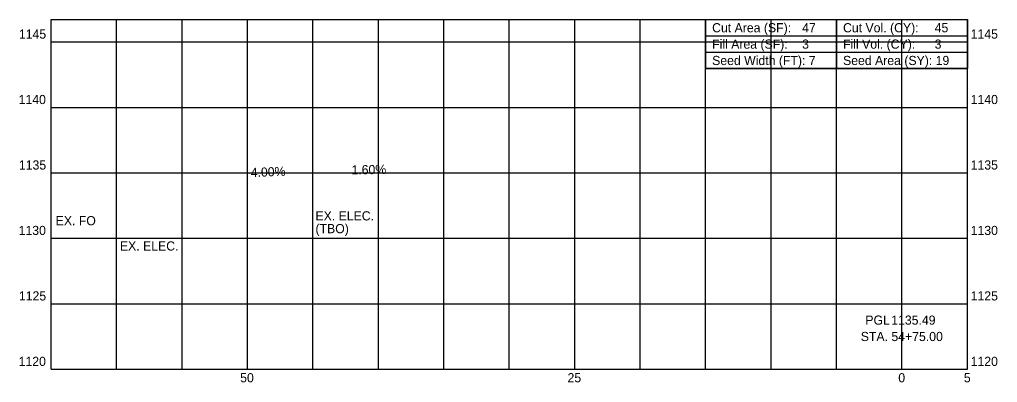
# Model space of a CAD drawing. Extents: x -67.4 to 7.3, y 1119 to 1146.7.
import ezdxf

# ---------------------------------------------------------------- set-up
doc = ezdxf.new("R2010")
doc.units = 0
for name, color, linetype in [('Default', 7, 'Continuous'), ('MD_P_Surface_Aggregate_Base', 7, 'Continuous'), ('MD_X_Concrete_Pavement', 7, 'Continuous'), ('SH_Data', 7, 'Continuous'), ('SH_Major_Grid_Line', 7, 'Continuous'), ('SH_Masking', 7, 'Continuous'), ('SH_Text', 7, 'Continuous')]:
    doc.layers.add(name, color=color, linetype=linetype)

msp = doc.modelspace()

# ---------------------------------------------------------------- linework, layer by layer
at = {"layer": 'Default'}
msp.add_circle((5, 1146.707), 0.000417, dxfattribs=at)
msp.add_circle((5, 1146.707), 0.000417, dxfattribs=at)
msp.add_circle((5, 1146.707), 0.000417, dxfattribs=at)
msp.add_circle((5, 1146.707), 0.000417, dxfattribs=at)
msp.add_circle((5, 1146.707), 0.000417, dxfattribs=at)
msp.add_circle((5, 1146.707), 0.000417, dxfattribs=at)
msp.add_circle((5, 1146.707), 0.000417, dxfattribs=at)
msp.add_circle((5, 1146.707), 0.000417, dxfattribs=at)
msp.add_circle((5, 1146.707), 0.000417, dxfattribs=at)
msp.add_circle((5, 1146.707), 0.000417, dxfattribs=at)
msp.add_circle((5, 1146.707), 0.000417, dxfattribs=at)
msp.add_circle((5, 1146.707), 0.000417, dxfattribs=at)
at = {"layer": 'SH_Data'}
for p, q in [((-15, 1146.707), (5, 1146.707)), ((-15, 1146.707), (-15, 1144.207)), ((-5, 1146.707), (-5, 1142.957)), ((5, 1146.707), (5, 1144.207)), ((-15, 1145.457), (5, 1145.457)), ((-15, 1144.207), (5, 1144.207)), ((-6.702, 1143.582), (-6.702, 1143.582)), ((2.946, 1143.582), (2.946, 1143.582))]:
    msp.add_line(p, q, dxfattribs=at)
msp.add_lwpolyline([(-15, 1144.207), (-15, 1142.957), (5, 1142.957), (5, 1144.207)], dxfattribs=at)
at = {"layer": 'SH_Major_Grid_Line'}
for p, q in [((-65, 1146.707), (5, 1146.707)), ((-65, 1120), (-65, 1146.707)), ((-60, 1120), (-60, 1146.707)), ((-55, 1120), (-55, 1146.707)), ((-50, 1120), (-50, 1146.707)), ((-45, 1120), (-45, 1146.707)), ((-40, 1120), (-40, 1146.707)), ((-35, 1120), (-35, 1146.707)), ((-30, 1120), (-30, 1146.707)), ((-25, 1120), (-25, 1146.707)), ((-20, 1120), (-20, 1146.707)), ((-15, 1120), (-15, 1146.707)), ((-10, 1120), (-10, 1146.707)), ((-5, 1120), (-5, 1146.707)), ((0, 1120), (0, 1146.707)), ((5, 1120), (5, 1146.707)), ((-65, 1145), (5, 1145)), ((-65, 1140), (5, 1140)), ((-65, 1135), (5, 1135)), ((-65, 1130), (5, 1130)), ((-65, 1125), (5, 1125)), ((-65, 1120), (5, 1120))]:
    msp.add_line(p, q, dxfattribs=at)
at = {"layer": 'SH_Masking'}
msp.add_lwpolyline([(-15, 1146.707), (5, 1146.707), (5, 1142.957), (-15, 1142.957)], close=True, dxfattribs=at)

# ---------------------------------------------------------------- texts
at = {"layer": 'MD_P_Surface_Aggregate_Base'}
for s, p in [('EX. ELEC.', (-44.804, 1131.364)), ('(TBO)', (-44.804, 1130.389)), ('EX. ELEC.', (-59.745, 1129.066))]:
    msp.add_text(s, height=0.7, dxfattribs=at).set_placement(p)
at = {"layer": 'MD_X_Concrete_Pavement'}
msp.add_text('EX. FO', height=0.7, dxfattribs=at).set_placement((-64.651, 1130.996))
at = {"layer": 'SH_Text'}
for s, p in [('Cut Area (SF):', (-14.5, 1145.732)), ('47', (-7.625, 1145.732)), ('Cut Vol. (CY):', (-4.5, 1145.732)), ('45', (2.5, 1145.732)), ('1145', (-67.461, 1145.25)), ('1145', (5.25, 1145.25)), ('Fill Area (SF):', (-14.5, 1144.482)), ('3', (-7.625, 1144.482)), ('Fill Vol. (CY):', (-4.5, 1144.482)), ('3', (2.5, 1144.482)), ('Seed Width (FT): 7', (-14.5, 1143.232)), ('Seed Area (SY): 19', (-4.5, 1143.232)), ('1140', (-67.482, 1140.25)), ('1140', (5.25, 1140.25)), ('1135', (-67.461, 1135.25)), ('1135', (5.25, 1135.25)), ('1130', (-67.482, 1130.25)), ('1130', (5.25, 1130.25)), ('1125', (-67.461, 1125.25)), ('1125', (5.25, 1125.25)), ('PGL ', (-2.796, 1123.4)), ('1135.49', (-0.818, 1123.4)), ('STA. 54+75.00', (-3.146, 1122.15)), ('1120', (-67.482, 1120.25)), ('1120', (5.25, 1120.25)), ('50', (-50.557, 1119)), ('25', (-25.547, 1119)), ('0', (-0.278, 1119)), ('5', (4.732, 1119))]:
    msp.add_text(s, height=0.7, dxfattribs=at).set_placement(p)
for s, rotation, p in [('1.60%', 0.91665, (-42.049, 1134.873)), ('4.00%', 2.29061, (-49.736, 1134.669))]:
    msp.add_text(s, height=0.7, rotation=rotation, dxfattribs=at).set_placement(p)

doc.saveas('drawing.dxf')
